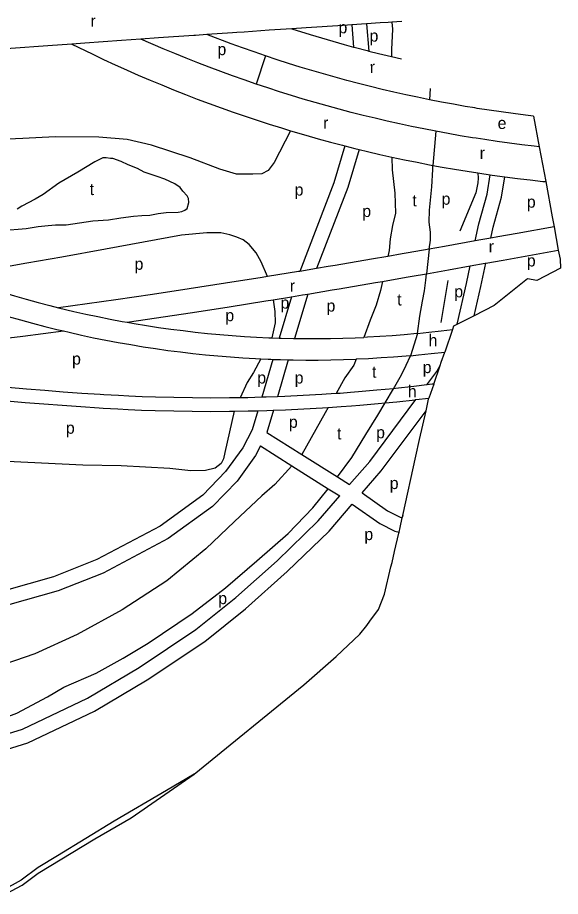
# Model space of a CAD drawing. Extents: x 157646 to 159241, y 379213 to 381217.
# Drawn here: x 158234.9 to 158418.3, y 379270.4 to 379567.3 of the extents above; entities that cross this region are included whole.
import ezdxf

# ---------------------------------------------------------------- set-up
doc = ezdxf.new("R2010")
doc.units = 0
for name, color, linetype in [('BLT_Basislijn', 7, 'Continuous'), ('BLT_Centroide', 7, 'Continuous'), ('BLT_Gemeentegrens', 7, 'Continuous'), ('BLT_Vlakafsluiter', 7, 'Continuous')]:
    doc.layers.add(name, color=color, linetype=linetype)

msp = doc.modelspace()

# ---------------------------------------------------------------- linework, layer by layer
at = {"layer": 'BLT_Basislijn'}
for p, q in [((158318.71, 379554.41), (158315.48, 379544.89)), ((158380.29, 379478.52), (158377.9, 379464.3))]:
    msp.add_line(p, q, dxfattribs=at)
for points in [[(158361.36, 379565.81), (158360.09, 379565.73), (158357.37, 379565.54), (158352.79, 379565.24)], [(158361.36, 379565.81), (158361.58, 379563.45), (158361.2, 379556.52), (158361.22, 379554.16)], [(158364.76, 379566.04), (158361.36, 379565.81)], [(158327.63, 379563.55), (158319.95, 379563.04), (158311.42, 379562.46), (158309.05, 379562.3), (158307.48, 379562.19), (158298.89, 379561.6)], [(158347.8, 379564.91), (158344.89, 379564.71), (158332.42, 379563.88), (158327.63, 379563.55)], [(158327.63, 379563.55), (158333.79, 379561.62), (158337.61, 379560.47), (158341.45, 379559.35), (158345.29, 379558.26), (158348.42, 379557.4)], [(158352.79, 379565.24), (158347.8, 379564.91)], [(158347.8, 379564.91), (158348.42, 379557.4)], [(158352.79, 379565.24), (158353.55, 379556.05)], [(158276.58, 379560.05), (158270.07, 379559.6), (158257.6, 379558.71), (158253.2, 379558.39)], [(158298.89, 379561.6), (158295.01, 379561.34), (158294.51, 379561.3), (158282.54, 379560.47), (158276.58, 379560.05)], [(158315.48, 379544.89), (158311.52, 379546.26), (158307.57, 379547.66), (158303.63, 379549.09), (158299.7, 379550.56), (158295.79, 379552.07), (158291.89, 379553.62), (158288.01, 379555.2), (158284.14, 379556.81), (158276.58, 379560.05)], [(158318.71, 379554.41), (158314.83, 379555.75), (158310.96, 379557.11), (158307.11, 379558.52), (158298.89, 379561.6)], [(158253.2, 379558.39), (158245.14, 379557.8), (158232.67, 379556.88), (158220.21, 379555.93), (158207.75, 379554.97), (158197.21, 379554.13)], [(158253.2, 379558.39), (158260.06, 379555.06), (158263.95, 379553.22), (158267.85, 379551.42), (158271.77, 379549.65), (158271.94, 379549.57), (158275.71, 379547.92), (158279.66, 379546.22), (158283.62, 379544.57), (158287.61, 379542.95), (158291.6, 379541.36), (158295.61, 379539.81), (158299.64, 379538.31), (158303.68, 379536.83), (158307.73, 379535.4), (158311.8, 379534), (158315.88, 379532.64), (158319.97, 379531.32), (158324.07, 379530.04), (158327.14, 379529.11)], [(158348.42, 379557.4), (158349.14, 379557.21), (158353, 379556.19), (158353.55, 379556.05)], [(158374.11, 379539.58), (158370.09, 379540.4), (158366.08, 379541.26), (158362.08, 379542.15), (158358.09, 379543.08), (158354.11, 379544.05), (158350.13, 379545.06), (158346.17, 379546.1), (158342.21, 379547.18), (158338.27, 379548.29), (158334.33, 379549.44), (158330.41, 379550.63), (158326.5, 379551.86), (158322.6, 379553.12), (158318.71, 379554.41)], [(158353.55, 379556.05), (158356.87, 379555.21), (158361.22, 379554.16)], [(158361.22, 379554.16), (158364.62, 379553.37)], [(158376.26, 379528.93), (158372.14, 379529.73), (158368.04, 379530.56), (158363.94, 379531.44), (158359.84, 379532.36), (158355.76, 379533.31), (158351.69, 379534.3), (158347.62, 379535.33), (158343.57, 379536.39), (158339.52, 379537.49), (158335.49, 379538.63), (158331.46, 379539.81), (158327.45, 379541.03), (158323.45, 379542.28), (158319.46, 379543.57), (158315.48, 379544.89)], [(158389.42, 379536.81), (158386.2, 379537.35), (158382.16, 379538.05), (158378.13, 379538.8), (158374.11, 379539.58)], [(158409.28, 379534.04), (158406.48, 379534.37), (158402.41, 379534.89), (158398.35, 379535.45), (158394.3, 379536.04), (158390.25, 379536.68), (158389.42, 379536.81)], [(158327.14, 379529.11), (158321.65, 379518.35), (158319.59, 379515.63), (158317.43, 379514.51), (158314.43, 379514.42), (158308.91, 379514.42), (158303.2, 379516.1), (158293.18, 379519.94), (158280.2, 379524.21), (158271.99, 379526.19), (158262.38, 379526.92), (158247.57, 379527.07), (158236.67, 379526.48), (158221.63, 379525.84), (158208.22, 379524.71), (158180.4, 379523.63), (158132.84, 379520.93)], [(158327.14, 379529.11), (158332.31, 379527.58), (158336.45, 379526.41), (158340.59, 379525.28), (158344.75, 379524.19), (158345.46, 379524.01)], [(158389.85, 379526.56), (158388.65, 379526.75), (158384.51, 379527.44), (158380.38, 379528.16), (158376.26, 379528.93)], [(158345.46, 379524.01), (158341.74, 379511.53), (158330.23, 379481.61)], [(158345.46, 379524.01), (158348.92, 379523.14), (158350.31, 379522.8)], [(158411.18, 379523.71), (158409.41, 379523.9), (158405.25, 379524.39), (158401.09, 379524.93), (158396.94, 379525.5), (158392.79, 379526.11), (158389.85, 379526.56)], [(158350.31, 379522.8), (158346.47, 379509.92), (158335.95, 379482.56)], [(158350.31, 379522.8), (158353.1, 379522.12), (158357.28, 379521.14), (158361.4, 379520.22)], [(158229.63, 379495.36), (158237.83, 379496.06), (158241.84, 379496.72), (158245.21, 379497.1), (158247.77, 379497.34), (158251.34, 379497.35), (158260.39, 379498.65), (158265.65, 379499.03), (158269.83, 379499.71), (158274.11, 379500.27), (158276.86, 379500.51), (158279.59, 379500.64), (158282.47, 379501.18), (158285.11, 379501.5), (158289.13, 379501.62), (158290.37, 379501.85), (158291.47, 379502.27), (158292.25, 379502.87), (158292.72, 379504.87), (158292.62, 379506.22), (158292.18, 379507.13), (158290.74, 379508.74), (158289.86, 379509.92), (158288.01, 379511.19), (158284.68, 379512.75), (158282.05, 379513.7), (158277.67, 379515.09), (158275.39, 379516.36), (158272.27, 379517.6), (158269.86, 379518.71), (158267.12, 379519.74), (158266.26, 379519.78), (158264.8, 379520.01), (158263.7, 379519.98), (158261.01, 379518.57), (158255.27, 379515.06), (158248.88, 379511.36), (158243.57, 379507.53), (158240.84, 379505.99), (158236.35, 379503.68), (158234.74, 379502.56)], [(158361.4, 379520.22), (158361.43, 379515.94), (158362.36, 379507.98), (158362.64, 379501.32), (158361.61, 379497.11), (158360.77, 379492.61), (158360.49, 379488.68), (158360.04, 379486.66)], [(158361.4, 379520.22), (158365.68, 379519.31), (158369.9, 379518.45), (158374.12, 379517.63), (158375.23, 379517.42)], [(158374.03, 379489.11), (158374.39, 379492.12), (158374.39, 379494.79), (158373.96, 379498.17), (158374.12, 379502.29), (158374.87, 379510.21), (158375.24, 379515.99), (158375.23, 379517.42)], [(158375.23, 379517.42), (158378.34, 379516.85), (158382.58, 379516.1), (158386.82, 379515.4), (158390.39, 379514.84)], [(158390.39, 379514.84), (158390.51, 379513.07), (158390.45, 379511.46), (158389.72, 379508.08), (158384.31, 379495.13)], [(158389.56, 379491.87), (158390.77, 379497.66), (158393.54, 379507.69), (158394.58, 379514.22)], [(158390.39, 379514.84), (158391.07, 379514.74), (158394.58, 379514.22)], [(158394.58, 379514.22), (158395.32, 379514.11), (158399.53, 379513.53)], [(158394.87, 379492.82), (158395.63, 379496.49), (158398.43, 379506.62), (158399.53, 379513.53)], [(158399.53, 379513.53), (158399.58, 379513.53), (158403.84, 379512.98), (158404.88, 379512.86)], [(158404.88, 379512.86), (158408.11, 379512.47), (158412.39, 379512.01), (158413.35, 379511.91)], [(158319.4, 379479.84), (158317.25, 379484.77), (158315.54, 379487.82), (158313.18, 379490.66), (158311.1, 379492.21), (158308.95, 379493.17), (158306.65, 379493.98), (158303.55, 379494.67), (158298.84, 379494.62), (158290.28, 379493.82), (158264.64, 379489.1), (158249.85, 379486.38), (158238.05, 379484.42), (158226.06, 379482.26), (158212.4, 379480.34)], [(158416.16, 379496.68), (158403.75, 379494.42), (158397.19, 379493.24)], [(158389.56, 379491.87), (158379.14, 379490.01), (158374.03, 379489.11)], [(158394.87, 379492.82), (158391.45, 379492.2), (158389.56, 379491.87)], [(158397.19, 379493.24), (158394.87, 379492.82)], [(158374.03, 379489.11), (158366.83, 379487.84), (158364.88, 379487.5), (158360.04, 379486.66)], [(158399.02, 379485.44), (158405.17, 379486.55), (158417.62, 379488.81)], [(158360.04, 379486.66), (158354.52, 379485.71), (158342.2, 379483.61), (158339.84, 379483.21), (158335.95, 379482.56)], [(158393.11, 379484.38), (158399.02, 379485.44)], [(158335.95, 379482.56), (158330.23, 379481.61)], [(158373.06, 379480.82), (158380.54, 379482.13), (158387.81, 379483.43)], [(158383.29, 379463.63), (158383.5, 379464.23), (158386.58, 379477.53), (158387.81, 379483.43)], [(158387.81, 379483.43), (158392.86, 379484.33), (158393.11, 379484.38)], [(158389.19, 379466.61), (158391.47, 379476.45), (158393.11, 379484.38)], [(158212.4, 379480.34), (158214.03, 379479.75), (158217.96, 379478.38), (158221.9, 379477.05), (158225.86, 379475.76), (158229.83, 379474.53), (158233.82, 379473.33), (158237.82, 379472.19), (158241.83, 379471.09), (158245.86, 379470.04), (158248.76, 379469.3)], [(158319.4, 379479.84), (158317.54, 379479.53), (158305.2, 379477.57), (158292.85, 379475.66), (158280.49, 379473.8), (158268.13, 379472.01), (158248.76, 379469.3)], [(158330.23, 379481.61), (158329.87, 379481.55), (158319.4, 379479.84)], [(158358.19, 379478.22), (158366.25, 379479.62), (158368.21, 379479.96), (158373.06, 379480.82)], [(158369.99, 379460.6), (158370.79, 379466.48), (158371.77, 379471.56), (158372.36, 379475.07), (158372.8, 379478.61), (158373.06, 379480.82)], [(158332.93, 379473.95), (158341.17, 379475.32), (158343.53, 379475.72), (158355.88, 379477.82), (158358.19, 379478.22)], [(158358.19, 379478.22), (158357.52, 379475.19), (158356.11, 379470.22), (158354.05, 379465.16), (158351.93, 379459.29)], [(158327.45, 379473.05), (158331.18, 379473.66), (158332.93, 379473.95)], [(158332.93, 379473.95), (158328.5, 379458.93)], [(158271.9, 379464.42), (158294.06, 379467.75), (158306.44, 379469.67), (158318.81, 379471.64), (158321.22, 379472.03)], [(158321.22, 379472.03), (158321.83, 379468), (158321.92, 379464.16), (158320.84, 379459.15)], [(158321.22, 379472.03), (158327.45, 379473.05)], [(158327.45, 379473.05), (158323.32, 379459.06)], [(158248.76, 379469.3), (158253.95, 379468.07), (158258.01, 379467.16), (158262.08, 379466.3), (158266.16, 379465.48), (158270.25, 379464.71), (158271.9, 379464.42)], [(158229.97, 379466.92), (158231.78, 379466.38), (158235.87, 379465.21), (158239.96, 379464.09), (158244.07, 379463.01), (158248.19, 379461.99), (158250.41, 379461.46)], [(158271.9, 379464.42), (158274.35, 379463.99), (158278.45, 379463.31), (158282.57, 379462.68), (158286.69, 379462.1), (158290.82, 379461.57), (158294.95, 379461.09), (158299.09, 379460.65), (158303.23, 379460.26), (158307.38, 379459.92), (158311.53, 379459.63), (158315.68, 379459.38), (158319.84, 379459.19), (158320.84, 379459.15)], [(158369.99, 379460.6), (158373.86, 379461.01), (158377.99, 379461.48), (158381.83, 379461.97)], [(158132.63, 379449.23), (158144.61, 379450.16), (158157.11, 379451.2), (158169.6, 379452.32), (158182.09, 379453.52), (158194.57, 379454.8), (158194.63, 379454.81), (158207.04, 379456.15), (158219.51, 379457.59), (158231.96, 379459.1), (158236.74, 379459.7), (158250.41, 379461.46)], [(158250.41, 379461.46), (158252.32, 379461.01), (158256.46, 379460.08), (158260.61, 379459.2), (158264.78, 379458.36), (158268.95, 379457.58), (158273.13, 379456.84), (158277.32, 379456.15), (158281.51, 379455.51), (158285.72, 379454.92), (158289.93, 379454.38), (158294.15, 379453.88), (158298.37, 379453.44), (158302.59, 379453.04), (158306.83, 379452.69), (158311.06, 379452.39), (158315.3, 379452.14), (158317.14, 379452.06)], [(158320.84, 379459.15), (158323.32, 379459.06)], [(158323.32, 379459.06), (158324, 379459.04), (158328.16, 379458.94), (158328.5, 379458.93)], [(158328.5, 379458.93), (158332.32, 379458.88), (158336.48, 379458.88), (158340.64, 379458.92), (158344.8, 379459.02), (158348.96, 379459.16), (158351.93, 379459.29)], [(158369.99, 379460.6), (158369.93, 379460.6), (158365.57, 379460.2), (158361.43, 379459.87), (158357.27, 379459.58), (158353.12, 379459.35), (158351.93, 379459.29)], [(158367.67, 379453.11), (158367.62, 379453.11), (158366.19, 379452.98), (158361.96, 379452.64), (158357.73, 379452.35), (158353.49, 379452.1), (158349.26, 379451.91)], [(158361.91, 379441.97), (158364.63, 379446.61), (158366.18, 379449.89), (158367.67, 379453.11)], [(158367.67, 379453.11), (158370.42, 379453.36), (158374.65, 379453.8), (158379.22, 379454.33)], [(158317.14, 379452.06), (158314.62, 379447.39), (158312.46, 379444.11), (158310.08, 379438.89)], [(158317.14, 379452.06), (158319.54, 379451.94), (158320.49, 379451.9), (158321.2, 379451.88)], [(158321.2, 379451.88), (158317.42, 379439.05)], [(158321.2, 379451.88), (158323.78, 379451.79), (158326.37, 379451.73)], [(158326.37, 379451.73), (158322.68, 379439.23)], [(158326.37, 379451.73), (158328.03, 379451.69), (158332.27, 379451.63), (158336.52, 379451.63), (158340.76, 379451.68), (158345.01, 379451.77), (158349.26, 379451.91)], [(158349.26, 379451.91), (158348.53, 379449.89), (158345.53, 379445.68), (158342.52, 379440.29)], [(158373.19, 379443.25), (158376.6, 379447.81), (158377.69, 379449.83)], [(158310.08, 379438.89), (158306.48, 379438.83), (158300.24, 379438.8), (158294, 379438.84), (158287.75, 379438.94), (158281.51, 379439.1), (158276.99, 379439.26), (158272.47, 379439.45), (158269.04, 379439.62), (158264.05, 379439.9), (158262.81, 379439.98), (158256.57, 379440.38), (158250.34, 379440.84), (158244.12, 379441.33), (158237.89, 379441.84), (158231.67, 379442.38)], [(158361.91, 379441.97), (158356.34, 379441.42), (158350.12, 379440.87), (158347.42, 379440.65), (158343.9, 379440.38), (158342.52, 379440.29)], [(158373.19, 379443.25), (158368.76, 379442.71), (158362.55, 379442.04), (158361.91, 379441.97)], [(158375.53, 379443.53), (158374.96, 379443.46), (158373.19, 379443.25)], [(158317.42, 379439.05), (158312.72, 379438.93), (158310.08, 379438.89)], [(158322.68, 379439.23), (158318.96, 379439.09), (158317.42, 379439.05)], [(158342.52, 379440.29), (158339.19, 379440.06), (158337.67, 379439.96), (158331.44, 379439.61), (158325.2, 379439.32), (158322.68, 379439.23)], [(158347.11, 379409.55), (158353.9, 379417.39), (158369.48, 379438.27)], [(158359.1, 379437.17), (158363.02, 379437.56), (158369.27, 379438.24), (158369.48, 379438.27)], [(158369.48, 379438.27), (158373.92, 379438.8)], [(158231.27, 379437.81), (158237.51, 379437.34), (158243.75, 379436.84), (158250.01, 379436.35), (158256.26, 379435.9), (158262.53, 379435.49), (158263.78, 379435.41), (158268.8, 379435.13), (158272.26, 379434.96), (158276.82, 379434.76), (158281.37, 379434.6), (158287.66, 379434.44), (158293.95, 379434.34), (158300.24, 379434.3), (158306.53, 379434.33), (158308.08, 379434.36)], [(158321.34, 379434.67), (158325.39, 379434.82), (158331.67, 379435.11), (158337.95, 379435.47), (158339.89, 379435.6)], [(158339.89, 379435.6), (158338.88, 379433.78), (158330.91, 379419.76)], [(158339.89, 379435.6), (158344.23, 379435.9), (158347.78, 379436.16), (158350.5, 379436.39), (158356.76, 379436.94), (158359.1, 379437.17)], [(158343.01, 379412.14), (158347.87, 379418.7), (158352.55, 379426.47), (158356.67, 379433.03), (158359.1, 379437.17)], [(158308.08, 379434.36), (158304.89, 379420.42), (158304.51, 379418.26), (158303.7, 379416.73), (158301.68, 379415.14), (158298.37, 379414.29), (158293.42, 379414.16), (158286.33, 379415.05), (158269.88, 379415.95), (158256.93, 379416.11), (158212.73, 379418.23), (158191.26, 379420.04), (158164.06, 379422.99), (158132.14, 379425.65), (158107.23, 379428.27), (158084.78, 379429.09), (158020.06, 379429.21), (157981.06, 379428.72), (157922.04, 379429.13), (157868.95, 379431.58), (157838.47, 379433.55)], [(158316.08, 379434.51), (158314.18, 379428.07), (158310.98, 379422), (158305.21, 379413.97), (158297.48, 379405.99), (158283.09, 379395.55), (158261.73, 379384.2), (158247.02, 379378.45), (158230.37, 379373.7)], [(158308.08, 379434.36), (158312.82, 379434.43), (158316.08, 379434.51)], [(158316.08, 379434.51), (158319.1, 379434.59), (158321.34, 379434.67)], [(158321.34, 379434.67), (158319.13, 379427.18)], [(158351.3, 379406.75), (158357.8, 379414.26), (158372.92, 379434.53)], [(158319.13, 379427.18), (158330.91, 379419.76)], [(158316.97, 379422.64), (158315.25, 379419.37), (158309.06, 379410.75), (158300.77, 379402.2), (158285.74, 379391.3), (158263.82, 379379.65), (158248.63, 379373.71), (158231.48, 379368.82)], [(158316.97, 379422.64), (158327.61, 379415.93)], [(158330.91, 379419.76), (158343.01, 379412.14)], [(158327.61, 379415.93), (158321.88, 379409.59), (158317.43, 379405.76), (158308.19, 379397.05), (158298.53, 379387.87), (158285.32, 379377.1), (158270.25, 379367.26), (158255.08, 379358.93), (158240.75, 379352.37), (158223.61, 379346.56), (158209.1, 379343.19), (158194.77, 379341.2)], [(158327.61, 379415.93), (158339.91, 379408.18)], [(158343.01, 379412.14), (158347.11, 379409.55)], [(158146.42, 379328.7), (158159.26, 379324.21), (158171.21, 379321.96), (158184.25, 379322.05), (158198.87, 379322.69), (158210.48, 379324.39), (158219.12, 379326.55), (158234.71, 379332.37), (158245.04, 379337.84), (158250.49, 379341.13), (158261.45, 379345.82), (158270.62, 379350.97), (158279.05, 379356.03), (158293.9, 379365.97), (158305.21, 379374.66), (158315.7, 379383.84), (158326.35, 379393.02), (158334.71, 379401.71), (158339.91, 379408.18)], [(158339.91, 379408.18), (158343.8, 379405.73)], [(158217.58, 379321.1), (158236.53, 379326.93), (158258.56, 379337.43), (158276.05, 379347.78), (158295.19, 379360.61), (158308.71, 379371.36), (158322.62, 379383.86), (158336.5, 379397.3), (158343.8, 379405.73)], [(158351.3, 379406.75), (158359.91, 379400.74), (158364.14, 379398.54), (158364.9, 379398.37)], [(158218.74, 379316.23), (158238.35, 379322.26), (158260.91, 379333.02), (158278.72, 379343.55), (158298.14, 379356.57), (158311.94, 379367.54), (158326.03, 379380.2), (158340.14, 379393.86), (158348.01, 379402.95)], [(158348.01, 379402.95), (158357.31, 379396.45), (158362.42, 379393.8), (158363.81, 379393.49)], [(158294.53, 379311.74), (158285.23, 379306.16), (158267.51, 379295.86), (158248.38, 379284.15), (158241.85, 379280.17), (158236.09, 379275.92), (158229.85, 379272.47)]]:
    msp.add_lwpolyline(points, dxfattribs=at)
at = {"layer": 'BLT_Gemeentegrens'}
msp.add_line((158365.07, 379399.14), (158364.97, 379398.7), dxfattribs=at)
for points in [[(158409.28, 379534.04), (158411.18, 379523.71)], [(158411.18, 379523.71), (158413.35, 379511.91)], [(158413.35, 379511.91), (158415.55, 379500), (158416.16, 379496.68)], [(158416.16, 379496.68), (158417.62, 379488.81)], [(158417.62, 379488.81), (158418.19, 379485.71), (158418.33, 379482.73), (158410.36, 379478.52), (158407.17, 379479.04), (158399.92, 379473.2)], [(158399.92, 379473.2), (158395.99, 379470.04), (158389.19, 379466.61)], [(158389.19, 379466.61), (158383.29, 379463.63)], [(158381.83, 379461.97), (158379.22, 379454.33)], [(158383.29, 379463.63), (158382.21, 379463.09), (158381.83, 379461.97)], [(158377.69, 379449.83), (158378.05, 379450.89), (158378.05, 379450.9), (158379.22, 379454.33)], [(158375.53, 379443.53), (158377.69, 379449.83)], [(158375.53, 379443.53), (158373.92, 379438.8)], [(158372.92, 379434.53), (158373.79, 379438.42), (158373.92, 379438.8)], [(158364.9, 379398.37), (158364.97, 379398.7), (158365.07, 379399.14), (158369.51, 379419.17), (158370.76, 379424.77), (158372.92, 379434.53)], [(158363.81, 379393.49), (158364.15, 379395.02), (158364.9, 379398.37)], [(158353.98, 379363.42), (158356.84, 379367.39), (158358.9, 379372.5), (158361.07, 379381.76), (158361.43, 379383.29), (158362.3, 379387.01), (158363.73, 379393.12), (158363.81, 379393.49)], [(158294.53, 379311.74), (158331.59, 379341.92), (158342.6, 379351.46), (158350.59, 379359.02), (158352.92, 379361.96), (158353.98, 379363.42)], [(158229.21, 379270.42), (158236.51, 379274.18), (158241.92, 379278.32), (158260.97, 379289.86), (158273.27, 379296.92), (158294.53, 379311.74)]]:
    msp.add_lwpolyline(points, dxfattribs=at)
at = {"layer": 'BLT_Vlakafsluiter'}
for p, q in [((158374.34, 379543.35), (158374.11, 379539.58)), ((158376.26, 379528.93), (158375.23, 379517.42)), ((158374.03, 379489.11), (158373.06, 379480.82)), ((158369.99, 379460.6), (158367.67, 379453.11)), ((158359.1, 379437.17), (158361.91, 379441.97))]:
    msp.add_line(p, q, dxfattribs=at)

# ---------------------------------------------------------------- texts
at = {"layer": 'BLT_Centroide'}
for s, p in [('r', (158259.54, 379564.22)), ('p', (158343.35, 379562.03)), ('p', (158353.83, 379559.22)), ('p', (158302.45, 379554.64)), ('r', (158353.9, 379548.63)), ('r', (158338.16, 379529.8)), ('e', (158397.12, 379529.7)), ('r', (158391.05, 379519.61)), ('t', (158259.26, 379507.38)), ('p', (158328.53, 379507.21)), ('t', (158368.29, 379503.57)), ('p', (158378.18, 379504.12)), ('p', (158406.99, 379503.11)), ('p', (158351.38, 379499.97)), ('r', (158394.09, 379488.03)), ('p', (158406.99, 379483.25)), ('p', (158274.44, 379482.13)), ('r', (158326.88, 379474.74)), ('t', (158363.19, 379470.08)), ('p', (158382.47, 379472.82)), ('p', (158323.75, 379469.01)), ('p', (158339.3, 379468.01)), ('p', (158305.12, 379464.76)), ('h', (158373.8, 379456.31)), ('p', (158253.33, 379450.1)), ('p', (158371.8, 379447.23)), ('p', (158315.9, 379443.7)), ('p', (158328.55, 379443.7)), ('t', (158354.66, 379445.67)), ('h', (158366.77, 379439.07)), ('p', (158251.24, 379426.75)), ('p', (158326.59, 379428.75)), ('t', (158342.83, 379424.83)), ('p', (158356.07, 379425.21)), ('p', (158360.66, 379408.06)), ('p', (158352.09, 379390.81)), ('p', (158302.73, 379369.16))]:
    msp.add_text(s, height=4, dxfattribs=at).set_placement(p)

doc.saveas('drawing.dxf')
